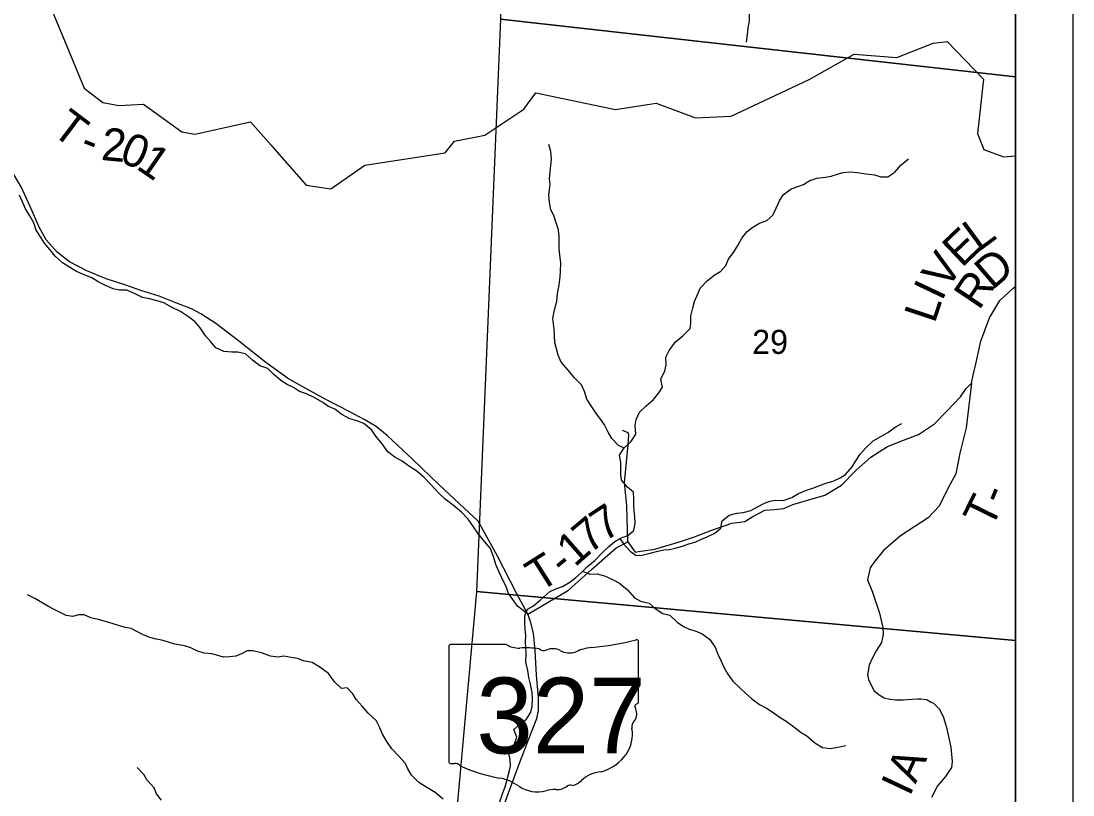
# Model space of a CAD drawing. Extents: x -13.1 to 43.1, y 0 to 22.
# Drawn here: x 7.172 to 9, y 17.45 to 18.795 of the extents above; entities that cross this region are included whole.
import ezdxf

# ---------------------------------------------------------------- set-up
doc = ezdxf.new("R2010")
doc.units = 0
for name, color, linetype in [('GM_X_Corporation', 7, 'Continuous'), ('GM_X_Minor_River', 7, 'Continuous'), ('GM_X_Section_Text', 7, 'Continuous'), ('GM_X_State_Location', 7, 'Continuous'), ('GM_X_State_Route', 7, 'Continuous'), ('GM_X_State_Shield', 7, 'Continuous'), ('GM_X_Township_Road', 7, 'Continuous'), ('GM_X_Township_Road_Text', 7, 'Continuous'), ('SH_Data', 7, 'Continuous')]:
    doc.layers.add(name, color=color, linetype=linetype)

msp = doc.modelspace()

# ---------------------------------------------------------------- linework, layer by layer
at = {"layer": 'GM_X_Corporation'}
for points in [[(8.9, 15.7487), (8.9, 20.9), (7.0804, 20.9), (7.0615, 20.6138), (7.0162, 19.896), (7.0106, 19.8452), (6.9616, 19.1692), (6.9507, 19.0184), (6.8365, 17.1257), (6.8234, 16.908), (6.7528, 15.9566), (7.8612, 15.855), (8.7782, 15.7572)], [(8.9, 15.7487), (8.9, 20.9), (7.0804, 20.9), (7.0615, 20.6138), (7.0162, 19.896), (7.0106, 19.8452), (6.9616, 19.1692), (6.9507, 19.0184), (6.8365, 17.1257), (6.8234, 16.908), (6.7528, 15.9566), (7.8612, 15.855), (8.7782, 15.7572)], [(8.9, 15.7481), (8.9, 20.9), (7.0807, 20.9), (7.0617, 20.6133), (7.0164, 19.8954), (7.0108, 19.8446), (6.9509, 19.0179), (6.8236, 16.9075), (6.7531, 15.956), (7.8614, 15.8545), (8.7784, 15.7567)], [(8.9, 18.698), (8.9, 19.7189), (8.018, 19.7768), (8.0053, 18.7983)], [(8.9, 17.7183), (8.9, 18.698), (8.0053, 18.7983), (7.9639, 17.8036)], [(8.9, 16.8362), (8.9, 17.7183), (7.9639, 17.8036), (7.8759, 16.828), (7.9357, 16.8233), (8.8534, 16.7472), (8.8951, 16.7437)]]:
    msp.add_lwpolyline(points, close=True, dxfattribs=at)
at = {"layer": 'GM_X_Minor_River'}
for p, q in [((8.0928, 18.5682), (8.0895, 18.5807)), ((8.0942, 18.5549), (8.0928, 18.5682)), ((8.093, 18.5443), (8.0942, 18.5549)), ((8.0906, 18.5212), (8.0914, 18.5337)), ((8.0914, 18.5337), (8.093, 18.5443)), ((8.0916, 18.5117), (8.0906, 18.5212)), ((8.0896, 18.4924), (8.0908, 18.5022)), ((8.0908, 18.5022), (8.0916, 18.5117)), ((8.0903, 18.4798), (8.0896, 18.4924)), ((8.0928, 18.4673), (8.0903, 18.4798)), ((8.0981, 18.457), (8.0928, 18.4673)), ((8.1018, 18.446), (8.0981, 18.457)), ((8.1062, 18.4323), (8.1018, 18.446)), ((8.1076, 18.4209), (8.1062, 18.4323)), ((8.1071, 18.4001), (8.1076, 18.4103)), ((8.1076, 18.4103), (8.1076, 18.4209)), ((8.1082, 18.3891), (8.1071, 18.4001)), ((8.1103, 18.3743), (8.1082, 18.3891)), ((8.1099, 18.3602), (8.1103, 18.3743)), ((8.1074, 18.3367), (8.109, 18.3504)), ((8.109, 18.3504), (8.1099, 18.3602)), ((8.1046, 18.3212), (8.1074, 18.3367)), ((8.1034, 18.3083), (8.1046, 18.3212)), ((8.0991, 18.2935), (8.1034, 18.3083)), ((8.0964, 18.2784), (8.0991, 18.2935)), ((8.0985, 18.2594), (8.0964, 18.2784)), ((8.0992, 18.2484), (8.0985, 18.2594)), ((8.0995, 18.2363), (8.0992, 18.2484)), ((8.1024, 18.2253), (8.0995, 18.2363)), ((8.1058, 18.2142), (8.1024, 18.2253)), ((8.111, 18.2021), (8.1058, 18.2142)), ((8.1238, 18.1879), (8.111, 18.2021)), ((8.1335, 18.1754), (8.1238, 18.1879)), ((8.1463, 18.1628), (8.1335, 18.1754)), ((8.1511, 18.1514), (8.1463, 18.1628)), ((8.1552, 18.1381), (8.1511, 18.1514)), ((8.1631, 18.1266), (8.1552, 18.1381)), ((8.1721, 18.1125), (8.1631, 18.1266)), ((8.1799, 18.1026), (8.1721, 18.1125)), ((8.1859, 18.0931), (8.1799, 18.1026)), ((8.693, 18.0906), (8.7025, 18.0958)), ((8.1923, 18.0805), (8.1859, 18.0931)), ((8.199, 18.0695), (8.1923, 18.0805)), ((8.6663, 18.0729), (8.6785, 18.08)), ((8.6785, 18.08), (8.693, 18.0906)), ((8.2103, 18.0573), (8.199, 18.0695)), ((8.22, 18.0526), (8.2103, 18.0573)), ((8.6393, 18.0526), (8.653, 18.0654)), ((8.653, 18.0654), (8.6663, 18.0729)), ((8.6225, 18.0307), (8.6305, 18.0424)), ((8.6305, 18.0424), (8.6393, 18.0526)), ((8.6164, 18.0201), (8.6225, 18.0307)), ((8.5954, 18.0013), (8.6049, 18.0069)), ((8.6049, 18.0069), (8.6164, 18.0201)), ((8.5479, 17.983), (8.5586, 17.9871)), ((8.5586, 17.9871), (8.5722, 17.9924)), ((8.5722, 17.9924), (8.5832, 17.9953)), ((8.5832, 17.9953), (8.5954, 18.0013)), ((8.4966, 17.9617), (8.5118, 17.967)), ((8.5118, 17.967), (8.5232, 17.9741)), ((8.5232, 17.9741), (8.5373, 17.9797)), ((8.5373, 17.9797), (8.5479, 17.983)), ((8.4401, 17.9447), (8.4519, 17.9507)), ((8.4519, 17.9507), (8.464, 17.957)), ((8.464, 17.957), (8.4735, 17.9608)), ((8.4735, 17.9608), (8.4834, 17.9626)), ((8.4834, 17.9626), (8.4966, 17.9617)), ((8.3903, 17.9264), (8.4029, 17.9362)), ((8.4029, 17.9362), (8.4162, 17.9399)), ((8.4162, 17.9399), (8.4272, 17.941)), ((8.4272, 17.941), (8.4401, 17.9447)), ((8.3777, 17.9049), (8.388, 17.9135)), ((8.388, 17.9135), (8.3903, 17.9264)), ((8.2127, 17.8959), (8.2189, 17.8862)), ((8.3446, 17.8899), (8.3549, 17.8944)), ((8.3549, 17.8944), (8.3644, 17.8989)), ((8.3644, 17.8989), (8.3777, 17.9049)), ((8.2189, 17.8862), (8.2305, 17.8736)), ((8.2764, 17.8733), (8.2892, 17.8758)), ((8.2892, 17.8758), (8.2991, 17.8769)), ((8.2991, 17.8769), (8.3086, 17.8788)), ((8.3086, 17.8788), (8.3215, 17.8825)), ((8.3215, 17.8825), (8.331, 17.8858)), ((8.331, 17.8858), (8.3446, 17.8899)), ((8.2305, 17.8736), (8.2411, 17.8663)), ((8.2411, 17.8663), (8.2517, 17.867)), ((8.2517, 17.867), (8.2654, 17.8703)), ((8.2654, 17.8703), (8.2764, 17.8733)), ((8.1481, 17.8388), (8.1606, 17.8338)), ((8.1606, 17.8338), (8.1731, 17.8341)), ((8.1731, 17.8341), (8.1863, 17.831)), ((8.1863, 17.831), (8.1999, 17.8245)), ((8.1999, 17.8245), (8.2123, 17.8183)), ((8.2123, 17.8183), (8.2259, 17.8065)), ((8.2259, 17.8065), (8.2383, 17.7927)), ((7.1965, 17.7915), (7.1833, 17.7981)), ((7.2101, 17.7831), (7.1965, 17.7915)), ((7.2199, 17.7773), (7.2101, 17.7831)), ((8.2383, 17.7927), (8.2488, 17.787)), ((8.2488, 17.787), (8.2636, 17.7831)), ((8.2636, 17.7831), (8.2741, 17.7743)), ((7.2297, 17.7723), (7.2199, 17.7773)), ((7.2406, 17.767), (7.2297, 17.7723)), ((7.2508, 17.762), (7.2406, 17.767)), ((8.2741, 17.7743), (8.2877, 17.7651)), ((8.2877, 17.7651), (8.2994, 17.7624)), ((7.2622, 17.7604), (7.2508, 17.762)), ((7.2724, 17.7633), (7.2622, 17.7604)), ((7.2822, 17.7629), (7.2724, 17.7633)), ((7.2936, 17.7579), (7.2822, 17.7629)), ((7.3064, 17.7548), (7.2936, 17.7579)), ((7.3193, 17.7513), (7.3064, 17.7548)), ((7.3306, 17.7482), (7.3193, 17.7513)), ((7.3435, 17.7439), (7.3306, 17.7482)), ((8.2994, 17.7624), (8.3126, 17.7505)), ((8.3126, 17.7505), (8.3231, 17.7429)), ((7.3537, 17.7412), (7.3435, 17.7439)), ((7.3635, 17.7392), (7.3537, 17.7412)), ((7.3737, 17.7339), (7.3635, 17.7392)), ((7.3835, 17.7289), (7.3737, 17.7339)), ((7.3959, 17.7239), (7.3835, 17.7289)), ((8.3231, 17.7429), (8.3329, 17.7383)), ((8.3329, 17.7383), (8.3435, 17.7352)), ((8.3435, 17.7352), (8.3556, 17.7301)), ((8.3556, 17.7301), (8.3688, 17.721)), ((7.4069, 17.7207), (7.3959, 17.7239)), ((7.4167, 17.7188), (7.4069, 17.7207)), ((7.4288, 17.7153), (7.4167, 17.7188)), ((7.4394, 17.7118), (7.4288, 17.7153)), ((7.4564, 17.709), (7.4394, 17.7118)), ((8.3688, 17.721), (8.3782, 17.7069)), ((7.4674, 17.7056), (7.4564, 17.709)), ((7.4779, 17.7002), (7.4674, 17.7056)), ((7.4904, 17.6963), (7.4779, 17.7002)), ((7.5037, 17.6951), (7.4904, 17.6963)), ((7.5142, 17.6924), (7.5037, 17.6951)), ((7.5241, 17.6896), (7.5142, 17.6924)), ((7.5552, 17.6951), (7.5453, 17.6914)), ((7.5654, 17.7004), (7.5552, 17.6951)), ((7.5753, 17.7003), (7.5654, 17.7004)), ((7.5904, 17.6972), (7.5753, 17.7003)), ((7.6059, 17.6914), (7.5904, 17.6972)), ((8.3782, 17.7069), (8.383, 17.6947)), ((8.383, 17.6947), (8.3886, 17.6825)), ((7.5347, 17.69), (7.5241, 17.6896)), ((7.5453, 17.6914), (7.5347, 17.69)), ((7.6187, 17.6894), (7.6059, 17.6914)), ((7.629, 17.6912), (7.6187, 17.6894)), ((7.6415, 17.6889), (7.629, 17.6912)), ((7.6524, 17.6869), (7.6415, 17.6889)), ((7.663, 17.6831), (7.6524, 17.6869)), ((7.6781, 17.6803), (7.663, 17.6831)), ((7.6917, 17.6719), (7.6781, 17.6803)), ((8.3886, 17.6825), (8.3934, 17.6719)), ((7.7064, 17.6608), (7.6917, 17.6719)), ((7.7176, 17.6459), (7.7064, 17.6608)), ((8.3934, 17.6719), (8.4005, 17.6597)), ((8.4005, 17.6597), (8.4092, 17.6475)), ((7.7293, 17.6352), (7.7176, 17.6459)), ((8.4092, 17.6475), (8.4212, 17.6364)), ((7.7388, 17.6359), (7.7293, 17.6352)), ((7.7489, 17.626), (7.7388, 17.6359)), ((7.7549, 17.6157), (7.7489, 17.626)), ((8.4212, 17.6364), (8.431, 17.6269)), ((8.431, 17.6269), (8.4423, 17.6169)), ((7.7651, 17.6043), (7.7549, 17.6157)), ((7.7756, 17.592), (7.7651, 17.6043)), ((8.4423, 17.6169), (8.4551, 17.6074)), ((8.4551, 17.6074), (8.4686, 17.6005)), ((8.4686, 17.6005), (8.4815, 17.5916)), ((7.7891, 17.5791), (7.7756, 17.592)), ((8.4815, 17.5916), (8.4913, 17.5848)), ((8.4913, 17.5848), (8.5018, 17.5782)), ((7.7955, 17.5665), (7.7891, 17.5791)), ((7.8003, 17.5555), (7.7955, 17.5665)), ((8.5018, 17.5782), (8.5173, 17.5664)), ((8.5173, 17.5664), (8.5278, 17.5587)), ((7.8078, 17.5429), (7.8003, 17.5555)), ((8.5278, 17.5587), (8.5376, 17.5526)), ((8.5376, 17.5526), (8.5515, 17.5404)), ((7.8164, 17.53), (7.8078, 17.5429)), ((7.8284, 17.5181), (7.8164, 17.53)), ((8.5515, 17.5404), (8.5651, 17.5327)), ((8.5651, 17.5327), (8.5783, 17.5307)), ((8.5783, 17.5307), (8.5916, 17.5329)), ((8.5916, 17.5329), (8.6053, 17.5362)), ((7.8397, 17.5055), (7.8284, 17.5181)), ((7.3855, 17.4857), (7.3742, 17.4976)), ((7.8446, 17.4956), (7.8397, 17.5055)), ((7.8505, 17.4842), (7.8446, 17.4956)), ((7.3911, 17.4762), (7.3855, 17.4857)), ((7.4035, 17.4621), (7.3911, 17.4762)), ((7.8633, 17.4716), (7.8505, 17.4842)), ((7.408, 17.4518), (7.4035, 17.4621)), ((7.8773, 17.4632), (7.8633, 17.4716)), ((7.892, 17.4544), (7.8773, 17.4632)), ((7.9055, 17.4429), (7.892, 17.4544)), ((7.4166, 17.4411), (7.408, 17.4518))]:
    msp.add_line(p, q, dxfattribs=at)
for points in [[(8.4279, 18.9248), (8.4217, 18.9124), (8.4194, 18.8972), (8.4185, 18.8862), (8.4188, 18.876), (8.4199, 18.8623), (8.4209, 18.8498), (8.4235, 18.8392), (8.4321, 18.8254), (8.4362, 18.8152), (8.4376, 18.8057), (8.4372, 18.7954), (8.4352, 18.7829), (8.434, 18.7716), (8.432, 18.7583)], [(8.0581, 17.5936), (8.0604, 17.6039), (8.0609, 17.6171), (8.0602, 17.6281), (8.0573, 17.6426), (8.0547, 17.654), (8.0526, 17.6665), (8.0496, 17.6809), (8.0501, 17.6957), (8.0494, 17.7063), (8.0491, 17.7158), (8.0492, 17.7272), (8.0482, 17.7378), (8.0475, 17.7485), (8.0476, 17.7613), (8.0522, 17.7731), (8.0625, 17.7787), (8.075, 17.7892), (8.0907, 17.8028), (8.1013, 17.808), (8.1131, 17.8121), (8.126, 17.8196), (8.1363, 17.8279), (8.1462, 17.8369), (8.1565, 17.8471), (8.1691, 17.8577), (8.1832, 17.872), (8.1935, 17.8818), (8.2038, 17.8904), (8.2137, 17.8964), (8.2266, 17.9009), (8.2372, 17.9099), (8.2392, 17.9224), (8.2389, 17.9334), (8.2375, 17.9441), (8.2368, 17.9543), (8.2373, 17.9649), (8.2362, 17.9763), (8.226, 17.9851), (8.2159, 17.9973), (8.2145, 18.0068), (8.2146, 18.0281), (8.2124, 18.0406), (8.2205, 18.0534), (8.2319, 18.064), (8.2407, 18.0772), (8.2393, 18.0924), (8.2409, 18.1026), (8.2467, 18.1151), (8.2577, 18.1256), (8.2711, 18.1373), (8.2802, 18.149), (8.2868, 18.1588), (8.2838, 18.1729), (8.2908, 18.1872), (8.2931, 18.1975), (8.2924, 18.2107), (8.2986, 18.2225), (8.3097, 18.2376), (8.3222, 18.2481), (8.3352, 18.2605), (8.336, 18.27), (8.3361, 18.2829), (8.3396, 18.2969), (8.3424, 18.3075), (8.3481, 18.3208), (8.3524, 18.331), (8.3646, 18.3434), (8.3768, 18.3536), (8.3882, 18.3603), (8.3966, 18.3701), (8.4016, 18.3811), (8.4115, 18.3947), (8.4177, 18.4049), (8.4246, 18.4177), (8.4341, 18.4294), (8.444, 18.437), (8.4551, 18.4437), (8.468, 18.4486), (8.4787, 18.4576), (8.4844, 18.4697), (8.4902, 18.4829), (8.4967, 18.4931), (8.5104, 18.5033), (8.5222, 18.5078), (8.5321, 18.5111), (8.5427, 18.5183), (8.5549, 18.5223), (8.57, 18.5238), (8.5799, 18.5256), (8.5909, 18.5289), (8.6008, 18.5319), (8.6129, 18.533), (8.625, 18.5318), (8.6405, 18.5298), (8.6553, 18.5278), (8.6662, 18.5243), (8.6783, 18.5242), (8.6905, 18.5328), (8.7012, 18.5445), (8.7142, 18.5558)], [(8.0497, 17.7667), (8.0352, 17.7781), (8.0269, 17.7899), (8.0194, 17.8002), (8.0157, 17.8105), (8.0075, 17.8276), (8.0023, 17.8386), (7.9975, 17.8508), (7.993, 17.8645), (7.9878, 17.8786), (7.9773, 17.8908), (7.9661, 17.9053), (7.9571, 17.9178), (7.9492, 17.9296), (7.9379, 17.9415), (7.9236, 17.9533), (7.9093, 17.9644), (7.8976, 17.9751), (7.8849, 17.9892), (7.8725, 18.0018), (7.86, 18.0129), (7.8453, 18.0221), (7.8348, 18.0301), (7.822, 18.037), (7.8099, 18.0466), (7.7998, 18.0603), (7.7889, 18.0737), (7.7818, 18.0843), (7.7679, 18.0958), (7.7558, 18.1004), (7.7437, 18.1039), (7.7297, 18.1112), (7.7173, 18.1204), (7.7067, 18.1254), (7.6966, 18.1319), (7.6819, 18.1411), (7.6683, 18.1473), (7.6562, 18.1515), (7.646, 18.1584), (7.6347, 18.1634), (7.6237, 18.1703), (7.6113, 18.1806), (7.6012, 18.191), (7.5872, 18.1956), (7.5744, 18.2059), (7.5624, 18.2166), (7.5484, 18.2197), (7.5385, 18.2194), (7.5245, 18.2207), (7.5109, 18.2272), (7.5023, 18.2375), (7.4929, 18.2478), (7.4835, 18.2619), (7.4749, 18.2722), (7.4632, 18.281), (7.4493, 18.2902), (7.4338, 18.2979), (7.4206, 18.3052), (7.4063, 18.3094), (7.3957, 18.3125), (7.3836, 18.3149), (7.3707, 18.321), (7.3564, 18.3276), (7.3431, 18.3273), (7.3322, 18.33), (7.3193, 18.3358), (7.3065, 18.3419), (7.2956, 18.3488), (7.282, 18.3542), (7.2688, 18.3596), (7.2552, 18.3681), (7.2446, 18.375), (7.2319, 18.3864), (7.2225, 18.3982), (7.2131, 18.4089), (7.2071, 18.4184), (7.1985, 18.4318), (7.1944, 18.4443), (7.1877, 18.4569), (7.1802, 18.4687), (7.1742, 18.482), (7.1698, 18.4926)], [(8.0043, 17.4381), (8.0094, 17.4536), (8.0136, 17.4638), (8.0171, 17.4771), (8.0202, 17.4899), (8.0229, 17.4998), (8.0219, 17.5108), (8.019, 17.5248), (8.0293, 17.5373), (8.0335, 17.5505), (8.0287, 17.5639), (8.0382, 17.5725), (8.0504, 17.5815), (8.0581, 17.5936)]]:
    msp.add_lwpolyline(points, dxfattribs=at)
at = {"layer": 'GM_X_State_Route'}
for points in [[(8.0483, 17.5306), (8.0549, 17.5475), (8.0685, 17.5831), (8.0713, 17.5967), (8.0715, 17.6198), (8.0681, 17.6582), (8.0654, 17.701), (8.0627, 17.7314), (8.0576, 17.7512), (8.0527, 17.7641), (8.0334, 17.8007), (8.0003, 17.8651), (7.9753, 17.9104), (7.9664, 17.9257), (7.942, 17.9483), (7.8995, 17.9884), (7.8526, 18.0336), (7.8091, 18.0742), (7.7895, 18.0907), (7.7688, 18.1026), (7.7424, 18.1165), (7.7028, 18.1366), (7.667, 18.1562), (7.6369, 18.1732), (7.5978, 18.2016), (7.55, 18.2392), (7.5109, 18.2695), (7.4849, 18.286), (7.4683, 18.2949), (7.4412, 18.3054), (7.4125, 18.317), (7.3823, 18.3264), (7.3544, 18.3361), (7.3204, 18.347), (7.2864, 18.361), (7.2563, 18.3764), (7.2352, 18.3933), (7.2161, 18.4147), (7.2038, 18.4368), (7.1882, 18.473), (7.1726, 18.5072), (7.1547, 18.5374)], [(7.8635, 16.7717), (7.871, 16.818), (7.8791, 16.8748), (7.8872, 16.9309), (7.8916, 16.9589), (7.9025, 16.9948), (7.9138, 17.022), (7.9354, 17.0655), (7.9597, 17.1142), (7.9666, 17.1289), (7.9702, 17.1463), (7.9745, 17.1982), (7.9783, 17.2494), (7.9838, 17.3062), (7.9884, 17.3517), (7.9935, 17.3763), (8.0037, 17.4107), (8.0227, 17.4629), (8.0421, 17.5147), (8.0483, 17.5306)]]:
    msp.add_lwpolyline(points, dxfattribs=at)
at = {"layer": 'GM_X_State_Shield'}
for p, q in [((8.0153, 17.7116), (7.9188, 17.7116)), ((8.2451, 17.6118), (8.2451, 17.7165)), ((7.9155, 17.7081), (7.9155, 17.508)), ((8.2451, 17.6119), (8.2451, 17.6118))]:
    msp.add_line(p, q, dxfattribs=at)
for centre, major_axis, start_param, end_param in [((7.9193, 17.7085), (0.00382, 0), 1.712693, 3.28349), ((8.0383, 17.7348), (0.037, 0), 4.042523, 4.731795), ((8.1277, 17.9844), (0.3495, 0), 4.814394, 5.042369), ((8.2414, 17.717), (0.00367, 0), 6.141152, 7.989035), ((8.0506, 17.5992), (0.133, 0), 1.404758, 1.657858), ((8.0807, 17.7096), (0.0107, 0), 3.836095, 5.185415), ((8.0964, 17.6864), (0.0222, 0), 0.950623, 2.079405), ((8.1251, 17.7182), (0.0267, 0), 4.081561, 5.145723), ((8.1723, 17.6504), (0.0703, 0), 1.699011, 2.107814), ((8.2443, 17.6041), (0.00568, 0), 1.883978, 3.671073), ((8.2081, 17.5909), (0.0341, 0), 5.934695, 6.695948), ((8.2412, 17.6114), (0.00393, 0), 5.05454, 6.418171), ((8.1473, 17.5547), (0.0874, 0), 5.101752, 6.440018), ((8.2582, 17.568), (0.0248, 0), 2.387724, 3.262537), ((7.9193, 17.5076), (0.00385, 0), 3.00124, 4.508301), ((7.9199, 17.528), (0.0294, 0), 4.665946, 4.897461), ((7.9259, 17.4964), (0.0106, 0), 0.519207, 1.627899), ((8.0598, 17.6762), (0.2524, 0), 4.195997, 4.488961), ((7.9845, 17.4181), (0.079, 0), 0.823519, 1.323587), ((8.1235, 17.4886), (0.0282, 0), 4.937069, 5.64225), ((8.1841, 17.4518), (0.0479, 0), 1.647645, 2.488434), ((8.0699, 17.4955), (0.0501, 0), 4.026481, 4.996735), ((8.0989, 17.4263), (0.0412, 0), 1.495662, 1.94098), ((8.1025, 17.4805), (0.0267, 0), 4.691044, 5.507374), ((8.1267, 17.4611), (0.00752, 0), 1.147584, 2.315152)]:
    msp.add_ellipse(centre, major_axis=major_axis, ratio=0.8, start_param=start_param, end_param=end_param, dxfattribs=at)
at = {"layer": 'GM_X_Township_Road'}
for points in [[(7.156, 18.9083), (7.2015, 18.8732), (7.2522, 18.7515), (7.2821, 18.6786), (7.3145, 18.6538), (7.3425, 18.6486), (7.3849, 18.6505), (7.4515, 18.6029), (7.4742, 18.5985), (7.571, 18.62), (7.6069, 18.5792), (7.6089, 18.577)], [(7.6089, 18.577), (7.668, 18.51), (7.7106, 18.5035), (7.7694, 18.5448), (7.9093, 18.5662), (7.9257, 18.5867), (7.978, 18.5971), (8.046, 18.6422), (8.0666, 18.6705), (8.2054, 18.6413), (8.2756, 18.6524), (8.3443, 18.6268), (8.406, 18.63), (8.5415, 18.6938), (8.6198, 18.7377), (8.6942, 18.7318), (8.7574, 18.7567), (8.7813, 18.7599), (8.8447, 18.6944), (8.8344, 18.5998), (8.8451, 18.5718), (8.8796, 18.5592), (8.9, 18.561)], [(8.8269, 18.1799), (8.8318, 18.2017), (8.8402, 18.2389), (8.8548, 18.2794), (8.8731, 18.3094), (8.8963, 18.331), (8.9, 18.3336)], [(8.245, 17.8729), (8.2735, 17.8773), (8.3183, 17.8905), (8.3423, 17.8988), (8.3723, 17.9105), (8.4076, 17.9222), (8.43, 17.9252), (8.4437, 17.9338), (8.4646, 17.9452), (8.4817, 17.9463), (8.4977, 17.9478), (8.5133, 17.9549), (8.5691, 17.9711), (8.5977, 17.9885), (8.6236, 18.0147), (8.6487, 18.037), (8.678, 18.0555), (8.7057, 18.0665), (8.7319, 18.0767), (8.7597, 18.0948), (8.781, 18.1168), (8.8046, 18.1418), (8.8146, 18.1562), (8.8237, 18.1657), (8.8269, 18.1799)], [(8.8237, 18.1657), (8.8146, 18.0884), (8.8035, 18.0438), (8.7965, 18.0081), (8.783, 17.9841), (8.7677, 17.9517), (8.7484, 17.9318), (8.7254, 17.9164), (8.7001, 17.9003), (8.6706, 17.8746), (8.654, 17.8543), (8.6477, 17.8448), (8.6432, 17.8239), (8.6518, 17.8023), (8.6638, 17.7659), (8.6697, 17.7409), (8.6701, 17.7288), (8.6672, 17.7147), (8.6582, 17.7002), (8.6511, 17.6872), (8.6462, 17.6758), (8.6433, 17.6587), (8.6445, 17.6507), (8.6538, 17.6314), (8.6633, 17.6239), (8.6721, 17.619), (8.6816, 17.6164), (8.6915, 17.6154), (8.7048, 17.6155), (8.72, 17.6163), (8.7302, 17.6172), (8.7359, 17.6172), (8.7458, 17.6158), (8.7468, 17.6152)], [(8.2267, 17.8901), (8.2247, 17.9526), (8.2206, 17.9932), (8.2273, 18.0585), (8.2285, 18.0759), (8.2273, 18.0797), (8.2175, 18.0835)], [(8.0527, 17.7641), (8.1233, 17.8059), (8.1629, 17.8411), (8.2066, 17.8794), (8.2267, 17.8901), (8.2393, 17.8721), (8.245, 17.8729)], [(8.7468, 17.6152), (8.7537, 17.6115), (8.7576, 17.6094), (8.7679, 17.5988), (8.7749, 17.5845), (8.78, 17.5674), (8.7878, 17.5329), (8.7903, 17.5082), (8.7888, 17.4976), (8.7783, 17.4819), (8.7647, 17.4659), (8.7542, 17.4457)]]:
    msp.add_lwpolyline(points, dxfattribs=at)
at = {"layer": 'SH_Data'}
for p, q in [((9, 21), (9, 14)), ((8.9, 20.9), (8.9, 14.1))]:
    msp.add_line(p, q, dxfattribs=at)

# ---------------------------------------------------------------- texts
at = {"layer": 'GM_X_Section_Text'}
msp.add_text('29', height=0.04186, rotation=0, dxfattribs=at).set_placement((8.4427, 18.2166))
at = {"layer": 'GM_X_State_Location'}
for s in ['s', 'r']:
    msp.add_text(s, height=0.000189, dxfattribs=at).set_placement((8.0766, 17.5947))
msp.add_text('327', height=0.000189, rotation=0, dxfattribs=at).set_placement((8.0097, 17.581))
at = {"layer": 'GM_X_State_Shield'}
msp.add_text('327', height=0.13184, dxfattribs=at).set_placement((7.9634, 17.5221))
at = {"layer": 'GM_X_Township_Road_Text'}
for s, rotation, p in [('T', 322.9193, (7.2233, 18.6004)), ('2', 354.5195, (7.3103, 18.5539)), ('-', 338.3996, (7.2717, 18.5666)), ('0', 337.4902, (7.3409, 18.5517)), ('1', 325.4266, (7.3704, 18.5398)), ('L', 36.4619, (8.8361, 18.3934)), ('E', 43.6907, (8.8068, 18.3652)), ('V', 56.6272, (8.7814, 18.3261)), ('D', 40.6685, (8.8602, 18.3267)), ('R', 55.957, (8.8367, 18.291)), ('I', 64.5504, (8.7724, 18.3068)), ('L', 71.519, (8.7596, 18.2682)), ('T', 63.8882, (8.8581, 17.9108)), ('-', 67.6926, (8.8785, 17.9527)), ('7', 33.3223, (8.1854, 17.8887)), ('7', 40.0305, (8.1602, 17.8674)), ('1', 41.4285, (8.1344, 17.8447)), ('T', 32.2765, (8.073, 17.8012)), ('-', 40.1331, (8.1157, 17.8289)), ('A', 65.753, (8.7265, 17.468)), ('I', 64.8027, (8.7162, 17.4459))]:
    msp.add_text(s, height=0.0568, rotation=rotation, dxfattribs=at).set_placement(p)

doc.saveas('drawing.dxf')
